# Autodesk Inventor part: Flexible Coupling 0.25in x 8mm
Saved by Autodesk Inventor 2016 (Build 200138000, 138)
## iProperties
Created: 2015-11
Part Number: Flexible Coupling 0.25in x 8mm
Material: Generic
Document SubType Name: Modeling
Designer: John
Density: 1 g/cm^3
Appearance: Default
Author: John
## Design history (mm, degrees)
feature "SOLID1"
body "Solid1"
